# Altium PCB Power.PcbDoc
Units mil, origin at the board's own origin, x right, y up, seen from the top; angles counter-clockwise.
Board outline 6000 x 4000 mil, 2 copper layers (Top Layer, Bottom Layer); 14 components, 4 nets, 58 pads, 0 vias.
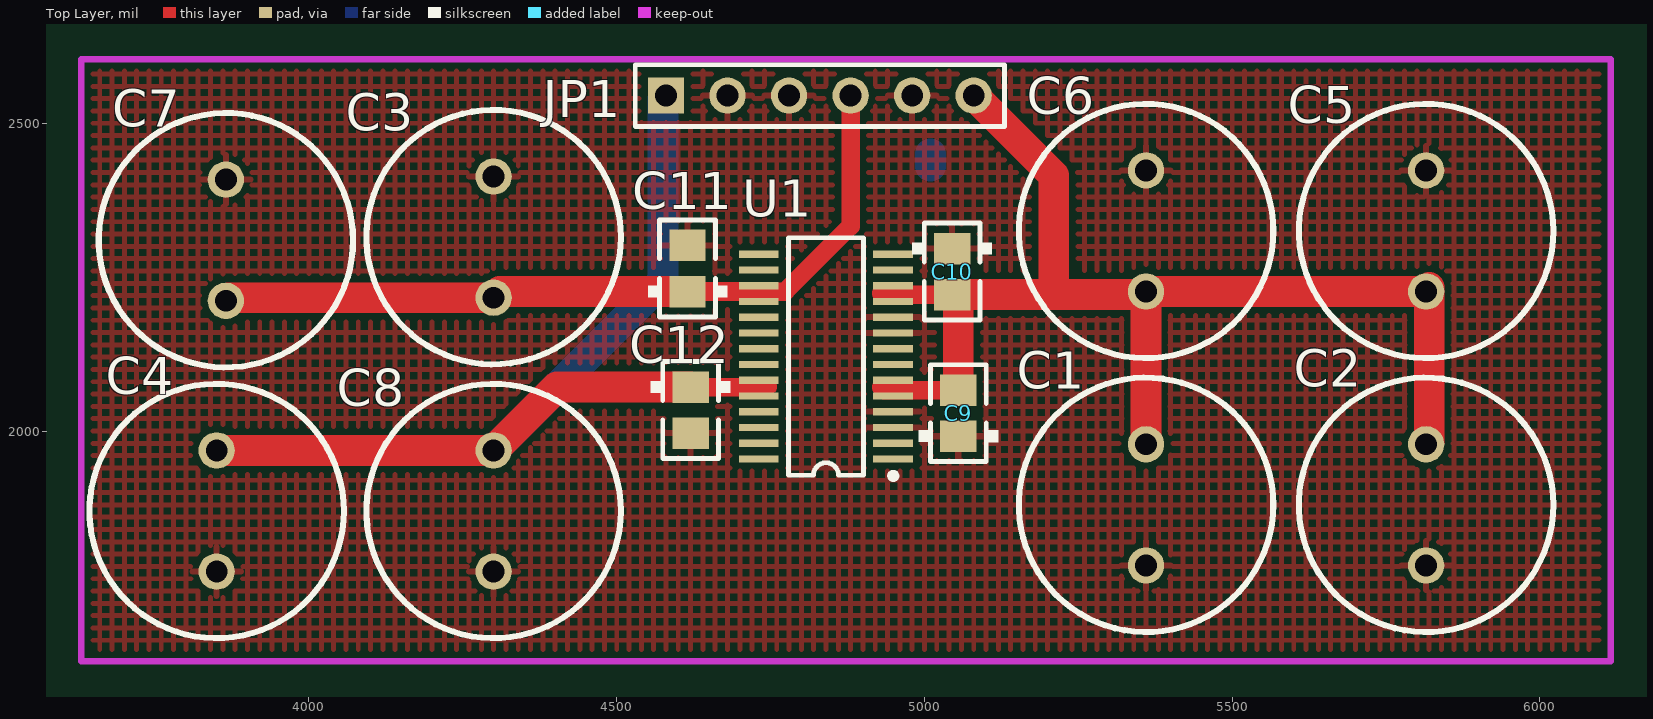
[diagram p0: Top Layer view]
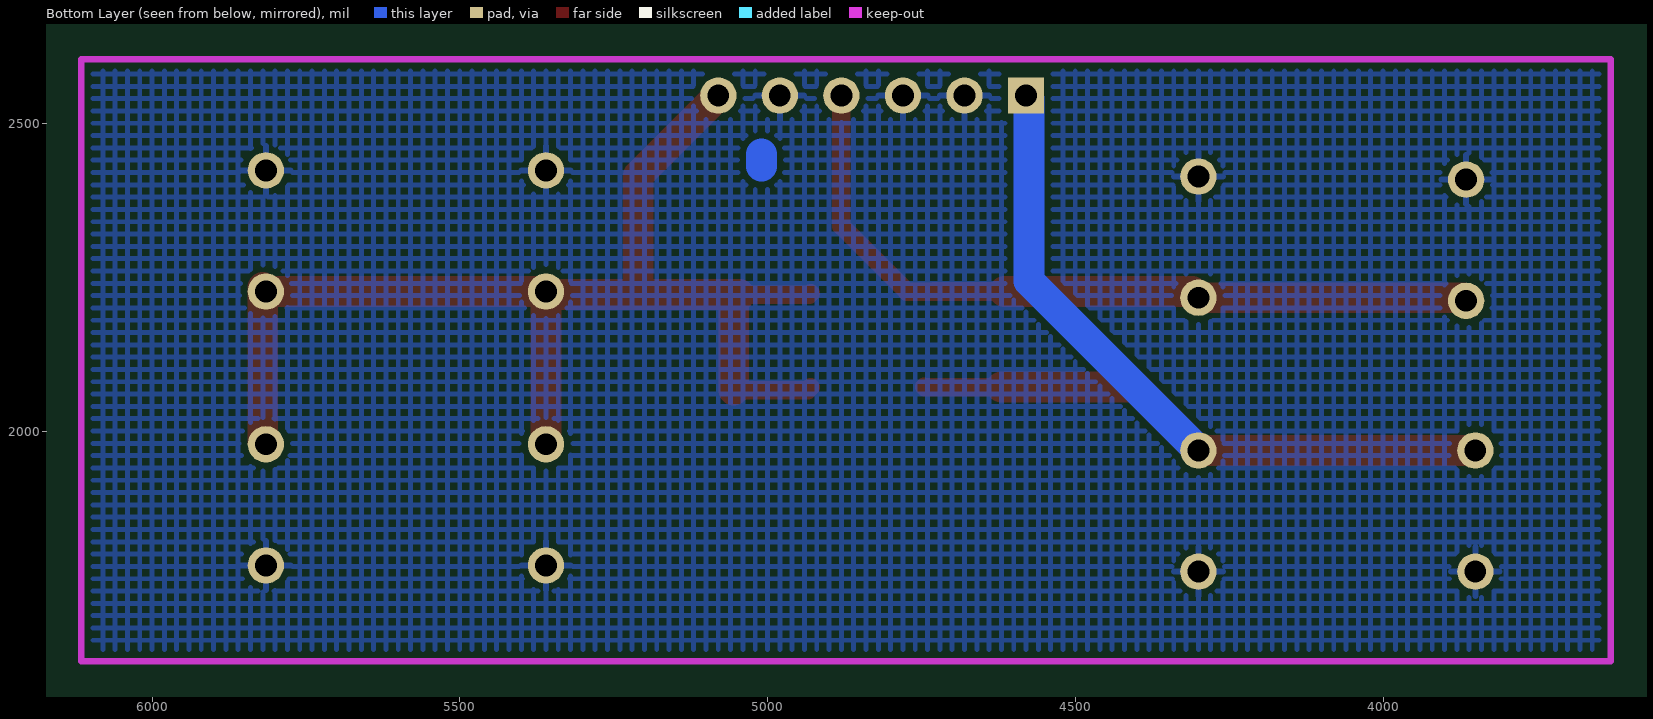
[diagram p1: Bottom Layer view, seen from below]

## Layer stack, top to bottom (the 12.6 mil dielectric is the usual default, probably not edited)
Top Layer: signal copper 1.4
Dielectric: dielectric 12.6, FR-4, Dk 4.8
Bottom Layer: signal copper 1.4

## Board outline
1000,1000 7000,1000 7000,5000 1000,5000

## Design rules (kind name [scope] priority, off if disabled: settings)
Clearance [All] p1: gap=10
ComponentClearance [All] p1: gap=10 collisioncheckmode=0
PolygonConnect [All] p1: connectstyle=Relief reliefconductorwidth=10 reliefentries=4 polygonreliefangle="90 Angle"
RoutingLayers [All] p1: top layer=Horizontal bottom layer=Vertical
RoutingVias [All] p1: holewidth=28 width=50 viastyle="Through Hole" minholewidth=28 minwidth=50 maxholewidth=28 maxwidth=50
SolderMaskExpansion [All] p1: expansion=4
TestPointUsage [All] p1: valid=0 allowmultiple=FALSE
Testpoint [All] p1: side=15 testpointundercomponent=TRUE minsize=40 maxsize=100 preferedsize=60 minholesize=0 maxholesize=40 preferedholesize=32 testpointgrid=1 style=1023 order=-539222988
Width [All] p1: maxlimit=50 minlimit=10 preferedwidth=30 bottomlayer_prefwidth=50 minimp=50.000000 maximp=50.000000 favimp=50.000000
16 further rules are at their usual default settings.

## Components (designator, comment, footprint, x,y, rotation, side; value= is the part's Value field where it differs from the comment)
C1 "10μ" RB5-10.5 5360,1880 r90 top
C2 "10μ" RB5-10.5 5815,1880 r90 top
C3 "10μ" RB5-10.5 4300,2315 r90 top
C4 "10μ" RB5-10.5 3850,1870 r270 top
C5 "47μ" RB5-10.5 5815,2325 r270 top
C6 "47μ" RB5-10.5 5360,2325 r270 top
C7 "47μ" RB5-10.5 3865,2310 r90 top
C8 "47μ" RB5-10.5 4300,1870 r270 top
C9 "104" CC2012-0805 5055,2029 r90 top
C10 "104" CC2012-0805 5045,2259 r270 top
C11 "104" CC2012-0805 4615,2264 r90 top
C12 "104" CC2012-0805 4620,2034 r270 top
JP1 "Header 6" HDR1X6 4580,2545 r0 top
U1 "TPS367D318" TSSO10X6-G28 4840,2121 r90 top

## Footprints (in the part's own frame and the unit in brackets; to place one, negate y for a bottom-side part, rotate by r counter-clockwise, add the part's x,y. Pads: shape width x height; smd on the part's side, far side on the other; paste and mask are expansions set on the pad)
CC2012-0805 [mm]
  rect 1.3x1.5 smd: 1(-0.95,0) 2(0.95,0)
  silkscreen extent -2,-1.65 2,1.64
HDR1X6 [mm]
  rect 1.5x1.5 hole 0.9: 1(0,0)
  round 1.5 hole 0.9: 2(2.54,0) 3(5.08,0) 4(7.62,0) 5(10.16,0) 6(12.7,0)
  silkscreen extent -1.27,-1.27 13.97,1.27
RB5-10.5 [mm]
  round 1.5 hole 0.9: 1(-2.5,0) 2(2.5,0)
  silkscreen extent -5.25,-5.25 5.25,5.25
TSSO10X6-G28 [mm]
  rect 0.3x1.65 smd: 1(-4.225,-2.775) 2(-3.575,-2.775) 3(-2.925,-2.775) 4(-2.275,-2.775) 5(-1.625,-2.775) 6(-0.975,-2.775) 7(-0.325,-2.775) 8(0.325,-2.775) 9(0.975,-2.775) 10(1.625,-2.775) 11(2.275,-2.775) 12(2.925,-2.775) 13(3.575,-2.775) 14(4.225,-2.775) 15(4.225,2.775) 16(3.575,2.775) 17(2.925,2.775) 18(2.275,2.775) 19(1.625,2.775) 20(0.975,2.775) 21(0.325,2.775) 22(-0.325,2.775) 23(-0.975,2.775) 24(-1.625,2.775) 25(-2.275,2.775) 26(-2.925,2.775) 27(-3.575,2.775) 28(-4.225,2.775)
  silkscreen extent -5.05,-2.9 4.9,1.55

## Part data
C1 C2 C3 C4 C5 C6 C7 C8: library part "CAPACITOR POL", "Capacitor"
C9 C10 C11 C12: library part CAP, "Capacitor"
JP1: "Header, 6-Pin"
U1: "POWRE"

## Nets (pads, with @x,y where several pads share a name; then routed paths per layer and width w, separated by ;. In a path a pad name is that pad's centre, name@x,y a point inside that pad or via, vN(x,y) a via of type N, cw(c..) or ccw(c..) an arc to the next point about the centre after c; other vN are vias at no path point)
1.8V: C4.1 C8.1 C12.1 JP1.1 U1.23 U1.24 | length 1630.5
  Top Layer w30: C12.1 4744.4,2071.4 4745,2072
  Top Layer w50: C4.1 C8.1 4402.98,2071.4 C12.1
  Bottom Layer w50: C8.1 4575,2243.43 4575,2540 JP1.1
3.3V: C3.1 C7.1 C11.1 JP1.4 U1.17 U1.18 | length 1397
  Top Layer w12: C11.1 4624.56,2236.16 U1.17
  Top Layer w30: C11.1 4773.6,2226.6 4880,2333 JP1.4
  Top Layer w50: C7.1 3870,2216.57 C3.1 4310.02,2226.6 C11.1
5V: C1.2 C2.2 C5.2 C6.2 C9.2 C10.2 JP1.6 U1.5 U1.6 U1.11 U1.12 | length 2064
  Top Layer w30: 4930,2071 4934.6,2066.4 C9.2 ; 4930,2224 4932.4,2221.6 C10.2
  Top Layer w50: C9.2 5055,2211.6 C10.2 5355.02,2221.6 C6.2 ; JP1.6 5210,2415 5210,2221.6 ; C1.2 C6.2 ; C2.2 5820,1983.43 5820,2233 5813.57,2226.57 C6.2
DGND: C1.1 C2.1 C3.2 C4.2 C5.1 C6.1 C7.2 C8.2 C9.1 C10.1 C11.2 C12.2 JP1.2 JP1.3 JP1.5 U1.3 U1.4 U1.9 U1.10
pads on no net: U1.1 U1.2 U1.7 U1.8 U1.13 U1.14 U1.15 U1.16 U1.19 U1.20 U1.21 U1.22 U1.25 U1.26 U1.27 U1.28
copper on no net: | length 20
  Bottom Layer w50: 5010,2430 5010,2450

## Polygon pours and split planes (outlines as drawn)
DGND on Top Layer (hatched 90Degree grid 20 track 8, remove dead copper): 3635,2594 3635,1636 6105,1636 6105,2594
DGND on Bottom Layer (hatched 90Degree grid 20 track 8, remove dead copper): 3640,2584 3640,1634 6115,1634 6115,2668 3635,2668 3635,2589

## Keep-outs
Keep-Out Layer:
  lines w10: 6115,2603 6115,1626 3630,1626 3630,2604 6115,2604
